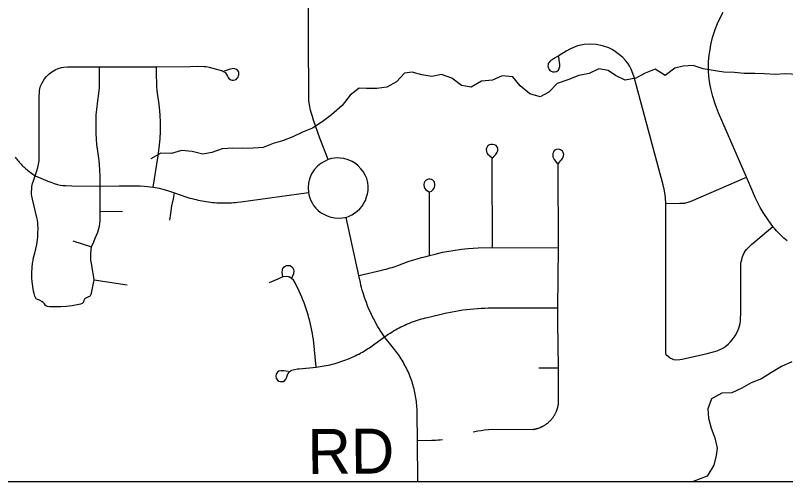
# Model space of a CAD drawing. Extents: x 0 to 34, y 0 to 22.
# Drawn here: x 4.7803 to 5.2675, y 14.1 to 14.3947 of the extents above; entities that cross this region are included whole.
import ezdxf

# ---------------------------------------------------------------- set-up
doc = ezdxf.new("R2010")
doc.units = 0
for name, color, linetype in [('GM_X_Minor_River', 7, 'Continuous'), ('GM_X_Rail_Line_Text', 7, 'Continuous'), ('GM_X_Township_Road', 7, 'Continuous'), ('GM_X_Township_Road_Text', 7, 'Continuous'), ('SH_Cut_Line', 7, 'Continuous'), ('SH_Data', 7, 'Continuous')]:
    doc.layers.add(name, color=color, linetype=linetype)

msp = doc.modelspace()

# ---------------------------------------------------------------- linework, layer by layer
at = {"layer": 'GM_X_Minor_River'}
for points in [[(5.27933, 14.3571), (5.26727, 14.35766), (5.26102, 14.35743), (5.25419, 14.35777), (5.24812, 14.35791), (5.24129, 14.35806), (5.23522, 14.35859), (5.22839, 14.35873), (5.22174, 14.35982), (5.21529, 14.36092), (5.20902, 14.36296), (5.20276, 14.36254), (5.19746, 14.36137), (5.19123, 14.35677), (5.18495, 14.36071), (5.17871, 14.35821), (5.17266, 14.35494), (5.16603, 14.35376), (5.15994, 14.35675), (5.15518, 14.35994), (5.1493, 14.36085), (5.14324, 14.35797), (5.13662, 14.35678), (5.12981, 14.35389), (5.123, 14.35157), (5.11772, 14.34622), (5.11224, 14.34315), (5.10578, 14.34519), (5.09968, 14.35009), (5.0949, 14.35594), (5.08826, 14.35646), (5.08202, 14.35376), (5.0752, 14.35315), (5.06858, 14.34931), (5.06251, 14.35041), (5.05641, 14.35492), (5.04976, 14.35734), (5.0437, 14.35616), (5.03743, 14.35707), (5.03135, 14.35892), (5.02643, 14.35813), (5.02134, 14.35278), (5.0153, 14.34933), (5.00885, 14.34853), (5.00241, 14.34848), (4.99766, 14.34864), (4.992, 14.34424), (4.98693, 14.33775), (4.98033, 14.33183), (4.97429, 14.32742), (4.96825, 14.3234), (4.96201, 14.32089), (4.95577, 14.318), (4.94934, 14.31549), (4.94328, 14.31375), (4.93704, 14.31124), (4.93078, 14.31081), (4.92415, 14.31058), (4.91789, 14.31073), (4.91107, 14.3103), (4.90463, 14.30798), (4.89876, 14.307), (4.89211, 14.30866), (4.88547, 14.30937), (4.87904, 14.30743), (4.87221, 14.30758), (4.86597, 14.30412)], [(5.27133, 14.17574), (5.2649, 14.17266), (5.25867, 14.16902), (5.25224, 14.16499), (5.24581, 14.16248), (5.23977, 14.15902), (5.23353, 14.15613), (5.22708, 14.1559), (5.22066, 14.15225), (5.21824, 14.14598), (5.21866, 14.1401), (5.2204, 14.13385), (5.22272, 14.1276), (5.22428, 14.12116), (5.22355, 14.11641), (5.22208, 14.11033), (5.21795, 14.10348), (5.20896, 14.1)]]:
    msp.add_lwpolyline(points, dxfattribs=at)
at = {"layer": 'GM_X_Rail_Line_Text'}
msp.add_lwpolyline([(6.04095, 15.63985), (5.15815, 15.63216), (4.9916, 15.62952), (4.91092, 15.62892), (4.86706, 15.62859), (4.81644, 15.62822), (4.76351, 15.62783), (4.71135, 15.62744), (4.67425, 15.62717), (4.62172, 15.62678), (4.57028, 15.6264), (4.49413, 15.62523), (4.43207, 15.62366), (4.42437, 15.62356), (4.29897, 15.62253), (4.30139, 15.38981), (4.3001, 14.71018), (4.30008, 14.70375), (4.29942, 14.35536), (4.29894, 14.1), (6.7466, 14.1)], dxfattribs=at)
at = {"layer": 'GM_X_Township_Road'}
for p, q in [((4.83385, 14.27067), (4.84795, 14.27087)), ((4.81662, 14.25217), (4.82845, 14.24832)), ((4.83018, 14.22756), (4.85103, 14.22431)), ((5.11143, 14.1719), (5.12377, 14.17192))]:
    msp.add_line(p, q, dxfattribs=at)
for points in [[(4.97807, 14.30357), (4.97292, 14.3171), (4.96892, 14.32839), (4.96815, 14.33077), (4.96738, 14.33329), (4.96701, 14.33478), (4.96626, 14.33813), (4.96591, 14.34093), (4.96584, 14.34296), (4.96577, 14.38025), (4.96577, 14.40337)], [(5.26844, 14.25217), (5.26743, 14.25303), (5.26644, 14.25391), (5.26547, 14.25481), (5.26451, 14.25572), (5.26357, 14.25665), (5.26264, 14.25759), (5.26173, 14.25855), (5.26084, 14.25953), (5.26072, 14.25966), (5.26066, 14.25974), (5.26059, 14.25981), (5.26052, 14.25989), (5.26045, 14.25997), (5.26039, 14.26004), (5.26032, 14.26012), (5.26025, 14.2602), (5.26018, 14.26027), (5.26012, 14.26035), (5.26005, 14.26043), (5.25998, 14.2605), (5.25992, 14.26058), (5.25985, 14.26066), (5.25938, 14.2612), (5.25696, 14.26476), (5.25326, 14.27018), (5.25148, 14.2732), (5.25016, 14.27575), (5.24831, 14.27962), (5.24676, 14.28326), (5.24281, 14.29239), (5.22494, 14.33317), (5.22308, 14.3382), (5.22145, 14.34339), (5.22022, 14.34842), (5.2196, 14.35159), (5.21921, 14.35445), (5.21882, 14.3591), (5.21875, 14.36204), (5.21882, 14.3656), (5.21921, 14.36947), (5.21967, 14.37287), (5.22029, 14.37612), (5.2213, 14.38076), (5.22293, 14.38587), (5.2244, 14.38951), (5.22587, 14.39268), (5.22795, 14.39681)], [(5.19455, 14.17812), (5.19313, 14.17897), (5.19235, 14.17961), (5.19185, 14.1804), (5.19163, 14.18111), (5.19163, 14.27573), (5.19153, 14.27928), (5.19135, 14.28135), (5.19071, 14.28478), (5.19006, 14.28755), (5.18757, 14.29696), (5.17325, 14.35025), (5.17161, 14.3556), (5.17081, 14.35799), (5.16983, 14.36065), (5.16872, 14.36275), (5.1677, 14.3645), (5.16621, 14.36622), (5.16449, 14.36799), (5.16239, 14.3698), (5.15993, 14.3717), (5.15786, 14.37305), (5.15565, 14.37426), (5.15174, 14.37554), (5.1476, 14.37633), (5.1439, 14.37654), (5.14005, 14.37626), (5.13592, 14.3754), (5.13147, 14.37354), (5.12879, 14.37211), (5.12435, 14.3694), (5.12135, 14.36757), (5.11989, 14.36671), (5.11904, 14.36613), (5.11839, 14.36557), (5.11786, 14.365), (5.11739, 14.36436), (5.11725, 14.36357), (5.11718, 14.36279), (5.11732, 14.36194), (5.11754, 14.3613), (5.11796, 14.36058), (5.11846, 14.35994), (5.11925, 14.35937), (5.12032, 14.35902), (5.12131, 14.35894), (5.12266, 14.35923), (5.12331, 14.35966), (5.12381, 14.36016), (5.12431, 14.36123), (5.12465, 14.36237), (5.12465, 14.36373), (5.12432, 14.36642), (5.12403, 14.3687)], [(4.79284, 14.29328), (4.7939, 14.29648), (4.79456, 14.29858), (4.795, 14.30057), (4.79533, 14.30277), (4.79539, 14.34412), (4.79547, 14.3456), (4.79561, 14.34699), (4.79577, 14.34832), (4.79627, 14.34997), (4.79699, 14.35157), (4.79782, 14.35306), (4.79881, 14.35461), (4.79991, 14.35604), (4.80168, 14.35775), (4.80339, 14.35903), (4.80549, 14.36024), (4.80742, 14.36112), (4.80952, 14.36173), (4.81101, 14.36195), (4.81327, 14.36217), (4.83348, 14.36222), (4.86952, 14.36223), (4.89088, 14.3625), (4.89519, 14.36256), (4.89972, 14.3625), (4.90099, 14.36239), (4.90286, 14.36206), (4.90529, 14.36145), (4.91132, 14.35956), (4.91203, 14.35925), (4.91269, 14.35881), (4.91323, 14.35832), (4.91374, 14.35742), (4.9144, 14.35626), (4.91495, 14.35549), (4.91539, 14.35488), (4.91595, 14.35439), (4.91667, 14.354), (4.91749, 14.35383), (4.91832, 14.35378), (4.9192, 14.35389), (4.91992, 14.35428), (4.92064, 14.35494), (4.92119, 14.35566), (4.92152, 14.35648), (4.92163, 14.3572), (4.92158, 14.35853), (4.92136, 14.35925), (4.9208, 14.36002), (4.92009, 14.36051), (4.91915, 14.36085), (4.91821, 14.36107), (4.91733, 14.36101), (4.91609, 14.36077), (4.91424, 14.36006), (4.91242, 14.35935)], [(4.83391, 14.28675), (4.83384, 14.29257), (4.83372, 14.29728), (4.83336, 14.30289), (4.83275, 14.3073), (4.83191, 14.31309), (4.83161, 14.31641), (4.83136, 14.31997), (4.8313, 14.32329), (4.83148, 14.33174), (4.83185, 14.33512), (4.83245, 14.34073), (4.83299, 14.34528), (4.83341, 14.34888), (4.8336, 14.35184), (4.83348, 14.36222)], [(4.86744, 14.28614), (4.87065, 14.3059), (4.87133, 14.31102), (4.87187, 14.31667), (4.87208, 14.32158), (4.87201, 14.32716), (4.8718, 14.33187), (4.8714, 14.33643), (4.87099, 14.34011), (4.87043, 14.34402), (4.86996, 14.34713), (4.86976, 14.34979), (4.86969, 14.35238), (4.86958, 14.35648), (4.86952, 14.36223)], [(5.0699, 14.13139), (5.07085, 14.13161), (5.07179, 14.13181), (5.07275, 14.132), (5.07488, 14.1324), (5.07706, 14.13274), (5.07957, 14.13295), (5.08219, 14.13306), (5.10774, 14.13301), (5.10807, 14.13306), (5.10839, 14.13311), (5.10872, 14.13317), (5.10904, 14.13323), (5.10936, 14.1333), (5.10968, 14.13338), (5.11, 14.13346), (5.11032, 14.13355), (5.11064, 14.13364), (5.11095, 14.13374), (5.11127, 14.13384), (5.11158, 14.13395), (5.11189, 14.13407), (5.11219, 14.13419), (5.1125, 14.13432), (5.1128, 14.13445), (5.1131, 14.13458), (5.1134, 14.13472), (5.11369, 14.13487), (5.11399, 14.13502), (5.11428, 14.13518), (5.11456, 14.13534), (5.11485, 14.13551), (5.11513, 14.13568), (5.11541, 14.13586), (5.11568, 14.13604), (5.11595, 14.13623), (5.11622, 14.13642), (5.11649, 14.13662), (5.11675, 14.13682), (5.11701, 14.13703), (5.11726, 14.13724), (5.11751, 14.13745), (5.11776, 14.13767), (5.118, 14.1379), (5.11824, 14.13812), (5.11848, 14.13836), (5.11871, 14.13859), (5.11893, 14.13883), (5.11916, 14.13907), (5.11937, 14.13932), (5.11959, 14.13957), (5.1198, 14.13983), (5.12, 14.14009), (5.1202, 14.14035), (5.1204, 14.14062), (5.12059, 14.14089), (5.12078, 14.14116), (5.12096, 14.14144), (5.12114, 14.14172), (5.12131, 14.142), (5.12148, 14.14228), (5.12164, 14.14257), (5.1218, 14.14286), (5.12195, 14.14316), (5.12209, 14.14345), (5.12224, 14.14375), (5.12237, 14.14405), (5.1225, 14.14436), (5.12263, 14.14467), (5.12275, 14.14497), (5.12286, 14.14528), (5.12297, 14.14559), (5.12308, 14.14591), (5.12318, 14.14623), (5.12327, 14.14654), (5.12336, 14.14686), (5.12344, 14.14718), (5.12352, 14.14751), (5.12359, 14.14783), (5.12365, 14.14815), (5.12371, 14.14848), (5.12376, 14.14881), (5.12381, 14.14913), (5.12385, 14.14946), (5.12389, 14.14979), (5.12377, 14.17192), (5.12347, 14.20081), (5.12343, 14.20979), (5.12382, 14.24767), (5.12356, 14.30005), (5.12383, 14.30108), (5.12445, 14.30198), (5.12501, 14.30267), (5.12542, 14.30329), (5.12632, 14.30432), (5.12687, 14.30529), (5.12701, 14.30599), (5.12715, 14.30673), (5.12708, 14.30736), (5.12687, 14.30805), (5.12632, 14.30887), (5.12577, 14.30936), (5.12508, 14.30977), (5.12439, 14.30998), (5.12356, 14.31005), (5.12259, 14.30998), (5.12184, 14.3097), (5.12115, 14.30922), (5.12059, 14.30832), (5.12032, 14.3075), (5.12018, 14.30625), (5.12025, 14.30522), (5.12059, 14.30439), (5.12107, 14.30356), (5.12321, 14.3008)], [(5.08211, 14.24802), (5.08187, 14.30145), (5.08197, 14.30409), (5.08206, 14.30453), (5.08229, 14.30484), (5.08264, 14.30513), (5.08319, 14.30574), (5.08394, 14.3066), (5.08445, 14.30727), (5.08514, 14.30815), (5.08543, 14.30906), (5.08554, 14.30992), (5.08543, 14.31061), (5.08526, 14.3113), (5.08491, 14.31193), (5.08439, 14.31239), (5.08325, 14.31296), (5.08211, 14.31319), (5.08096, 14.31313), (5.07999, 14.3129), (5.07947, 14.3125), (5.07895, 14.31198), (5.07844, 14.31113), (5.07815, 14.3101), (5.07832, 14.30866), (5.07861, 14.30792), (5.07901, 14.30729), (5.08033, 14.30597), (5.08193, 14.30457)], [(4.78014, 14.30506), (4.78064, 14.3044), (4.78115, 14.30375), (4.78167, 14.30311), (4.7822, 14.30248), (4.78274, 14.30185), (4.7833, 14.30124), (4.78386, 14.30064), (4.78444, 14.30004), (4.78502, 14.29946), (4.78562, 14.29888), (4.78623, 14.29832), (4.78684, 14.29777), (4.78747, 14.29723), (4.7881, 14.2967), (4.79284, 14.29328), (4.79649, 14.29173), (4.80074, 14.28991), (4.80278, 14.28919), (4.80482, 14.28853), (4.80692, 14.28787), (4.80875, 14.28748), (4.81029, 14.28726), (4.81197, 14.28709), (4.81606, 14.28689), (4.83391, 14.28675), (4.84598, 14.28689), (4.85599, 14.28696), (4.85919, 14.28689), (4.86199, 14.28675), (4.86744, 14.28614), (4.87126, 14.28546), (4.87439, 14.28471), (4.8778, 14.28362), (4.881, 14.28258), (4.88821, 14.28002), (4.88946, 14.27961), (4.89073, 14.27923), (4.892, 14.27887), (4.89328, 14.27853), (4.89456, 14.27822), (4.89585, 14.27792), (4.89714, 14.27765), (4.89844, 14.2774), (4.89975, 14.27718), (4.90105, 14.27697), (4.90236, 14.27679), (4.90368, 14.27663), (4.90499, 14.27649), (4.90631, 14.27638), (4.90764, 14.27629), (4.90896, 14.27622), (4.91028, 14.27618), (4.91558, 14.27623), (4.91691, 14.2763), (4.91823, 14.27639), (4.91955, 14.2765), (4.92087, 14.27664), (4.92281, 14.27689), (4.96561, 14.28272)], [(4.98946, 14.267), (4.99143, 14.26783), (4.99319, 14.26873), (4.99483, 14.26972), (4.99652, 14.27087), (4.99816, 14.27247), (4.99968, 14.27415), (5.0007, 14.27595), (5.00167, 14.27776), (5.00248, 14.27993), (5.00301, 14.28189), (5.00336, 14.28401), (5.0034, 14.28653), (5.00317, 14.28907), (5.00255, 14.29154), (5.00165, 14.29378), (5.00019, 14.29599), (4.99883, 14.29777), (4.99722, 14.29952), (4.99542, 14.30098), (4.99327, 14.30238), (4.99075, 14.30345), (4.98796, 14.30423), (4.98577, 14.30455), (4.98389, 14.30462), (4.98209, 14.30446), (4.98028, 14.30418), (4.97807, 14.30357), (4.97358, 14.3011), (4.97132, 14.29939), (4.96923, 14.29715), (4.9676, 14.29452), (4.96637, 14.29138), (4.96578, 14.28874), (4.96554, 14.28583), (4.96561, 14.28272), (4.96611, 14.28052), (4.96647, 14.27937), (4.96698, 14.27802), (4.96793, 14.27617), (4.96895, 14.27453), (4.97031, 14.27293), (4.97166, 14.27158), (4.97334, 14.27007), (4.97503, 14.26916), (4.97745, 14.26805), (4.97979, 14.26719), (4.98229, 14.26674), (4.98578, 14.26653), (4.98876, 14.26684), (4.98946, 14.267)], [(4.82469, 14.21589), (4.82408, 14.21528), (4.82359, 14.2144), (4.82331, 14.21351), (4.82298, 14.2129), (4.82254, 14.21257), (4.82143, 14.21209), (4.81622, 14.21118), (4.81245, 14.21071), (4.80908, 14.21048), (4.80549, 14.21039), (4.80195, 14.21043), (4.80059, 14.21062), (4.79994, 14.21095), (4.79943, 14.21137), (4.79873, 14.21239), (4.79793, 14.21328), (4.7971, 14.21393), (4.79565, 14.21459), (4.79434, 14.2151), (4.7935, 14.21557), (4.79303, 14.21627), (4.79266, 14.21724), (4.7922, 14.21893), (4.79182, 14.22047), (4.79126, 14.22336), (4.79089, 14.2263), (4.7907, 14.22886), (4.79061, 14.23218), (4.79084, 14.2353), (4.79117, 14.23801), (4.79149, 14.23983), (4.79182, 14.24156), (4.79254, 14.24447), (4.79317, 14.24706), (4.79383, 14.24991), (4.79434, 14.2529), (4.79453, 14.255), (4.79458, 14.25658), (4.79467, 14.26036), (4.7946, 14.26205), (4.79444, 14.26363), (4.7942, 14.2652), (4.79392, 14.26703), (4.7928, 14.27147), (4.79189, 14.27496), (4.79103, 14.27846), (4.7907, 14.28033), (4.79056, 14.28168), (4.79065, 14.28649), (4.79103, 14.28836), (4.79168, 14.29022), (4.79284, 14.29328)], [(5.04232, 14.24291), (5.04214, 14.28071), (5.04219, 14.28259), (5.0422, 14.28291), (5.04221, 14.28306), (5.04231, 14.28315), (5.04255, 14.28324), (5.04347, 14.28368), (5.04446, 14.2846), (5.04538, 14.2859), (5.04561, 14.28697), (5.04568, 14.28811), (5.04545, 14.28911), (5.04515, 14.2898), (5.04438, 14.29048), (5.04347, 14.29094), (5.0427, 14.29109), (5.04187, 14.29109), (5.04095, 14.29094), (5.04003, 14.29048), (5.03927, 14.28972), (5.03889, 14.28895), (5.03866, 14.28811), (5.03866, 14.2875), (5.03896, 14.28621), (5.03927, 14.28537), (5.03995, 14.28437), (5.04206, 14.28311)], [(5.19163, 14.27573), (5.2006, 14.2759), (5.20353, 14.27608), (5.20589, 14.27655), (5.20771, 14.27717), (5.24281, 14.29239)], [(4.82469, 14.21589), (4.82552, 14.21644), (4.82668, 14.21693), (4.82729, 14.21721), (4.82778, 14.21765), (4.82817, 14.21848), (4.82839, 14.2192), (4.83018, 14.22756), (4.82966, 14.23054), (4.82913, 14.23389), (4.82859, 14.23675), (4.82808, 14.23999), (4.82801, 14.24222), (4.82808, 14.2444), (4.82845, 14.24832), (4.82982, 14.25162), (4.83081, 14.25386), (4.83243, 14.25772), (4.83312, 14.25996), (4.83349, 14.26139), (4.83374, 14.26325), (4.83386, 14.265), (4.83392, 14.26692), (4.83385, 14.27067), (4.83391, 14.28675)], [(4.87794, 14.26534), (4.87858, 14.26943), (4.87935, 14.27441), (4.88021, 14.27868), (4.881, 14.28258)], [(5.03488, 14.1), (5.03465, 14.12604), (5.03451, 14.14254), (5.03446, 14.14486), (5.0344, 14.14602), (5.03433, 14.14717), (5.03423, 14.14833), (5.03412, 14.14948), (5.03398, 14.15063), (5.03383, 14.15178), (5.03365, 14.15293), (5.03345, 14.15407), (5.03324, 14.15521), (5.033, 14.15634), (5.03275, 14.15747), (5.03248, 14.1586), (5.03218, 14.15972), (5.03187, 14.16084), (5.03153, 14.16195), (5.03118, 14.16305), (5.03081, 14.16415), (5.03042, 14.16524), (5.03001, 14.16632), (5.02958, 14.1674), (5.02913, 14.16847), (5.02866, 14.16953), (5.02818, 14.17058), (5.02767, 14.17162), (5.02715, 14.17266), (5.02661, 14.17368), (5.02605, 14.1747), (5.02548, 14.17571), (5.02488, 14.1767), (5.02427, 14.17769), (5.02365, 14.17866), (5.02301, 14.17963), (5.02235, 14.18058), (5.02168, 14.18152), (5.02098, 14.18245), (5.02028, 14.18336), (5.01956, 14.18427), (5.01862, 14.1854), (5.01691, 14.18748), (5.01589, 14.18878), (5.01489, 14.19009), (5.01386, 14.1915), (5.01297, 14.19277), (5.01204, 14.19414), (5.01114, 14.19552), (5.01026, 14.19692), (5.00941, 14.19833), (5.00858, 14.19976), (5.00778, 14.2012), (5.007, 14.20265), (5.00625, 14.20412), (5.00552, 14.20561), (5.00483, 14.2071), (5.00415, 14.2086), (5.00351, 14.21012), (5.00289, 14.21165), (5.00229, 14.21318), (5.00173, 14.21473), (5.00119, 14.21628), (5.00068, 14.21784), (5.0002, 14.21942), (4.99974, 14.221), (4.99931, 14.22259), (4.99891, 14.22418), (4.99854, 14.22579), (4.99754, 14.23033), (4.98946, 14.267)], [(5.19455, 14.17812), (5.19539, 14.17772), (5.19655, 14.17719), (5.19776, 14.17698), (5.20068, 14.17719), (5.20196, 14.17741), (5.21793, 14.18091), (5.22097, 14.18174), (5.2241, 14.18267), (5.2278, 14.18437), (5.22958, 14.18559), (5.2313, 14.18701), (5.23249, 14.18817), (5.23372, 14.18951), (5.2355, 14.19214), (5.23692, 14.19449), (5.23785, 14.19691), (5.23871, 14.19991), (5.23893, 14.20147), (5.23906, 14.20325), (5.23915, 14.20589), (5.23908, 14.23455), (5.23914, 14.23624), (5.23927, 14.23831), (5.2397, 14.24009), (5.24006, 14.24159), (5.24063, 14.24308), (5.24134, 14.24458), (5.24198, 14.24565), (5.24277, 14.24664), (5.24359, 14.24754), (5.2459, 14.24978), (5.25938, 14.2612)], [(4.99754, 14.23033), (5.01219, 14.2337), (5.01348, 14.234), (5.01475, 14.23433), (5.01602, 14.23467), (5.01728, 14.23504), (5.01854, 14.23544), (5.01979, 14.23585), (5.02212, 14.23669), (5.026, 14.23811), (5.02878, 14.23906), (5.03158, 14.23996), (5.03439, 14.24082), (5.03722, 14.24162), (5.04005, 14.24238), (5.04232, 14.24291), (5.04589, 14.24376), (5.05055, 14.24493), (5.05725, 14.24618), (5.0624, 14.24687), (5.06676, 14.24727), (5.07311, 14.24773), (5.08211, 14.24802), (5.12382, 14.24767)], [(4.94937, 14.22945), (4.94912, 14.23231), (4.94921, 14.2337), (4.94953, 14.23464), (4.95006, 14.23546), (4.95088, 14.23619), (4.95183, 14.23656), (4.95293, 14.23666), (4.95403, 14.23653), (4.95526, 14.23584), (4.95586, 14.23508), (4.95623, 14.23411), (4.95636, 14.23313), (4.95617, 14.23143), (4.95542, 14.22948), (4.95501, 14.22842)], [(4.97057, 14.17241), (4.96883, 14.18973), (4.96852, 14.1917), (4.96817, 14.19366), (4.96779, 14.19561), (4.96738, 14.19756), (4.96694, 14.19953), (4.96648, 14.2015), (4.96597, 14.20345), (4.96542, 14.20536), (4.96482, 14.20727), (4.9642, 14.20918), (4.96356, 14.21107), (4.96289, 14.21294), (4.96218, 14.21481), (4.96145, 14.21667), (4.96069, 14.21851), (4.95989, 14.22034), (4.95724, 14.2257), (4.9562, 14.22724), (4.95501, 14.22842), (4.95425, 14.22888), (4.95321, 14.22938), (4.95192, 14.22963), (4.94937, 14.22945), (4.94795, 14.22888), (4.94628, 14.22803), (4.94386, 14.22683), (4.9408, 14.22554)], [(4.95283, 14.16953), (4.95, 14.16999), (4.94848, 14.17007), (4.94703, 14.16984), (4.94603, 14.16923), (4.94535, 14.168), (4.94512, 14.16671), (4.94535, 14.16533), (4.94603, 14.16411), (4.94688, 14.16342), (4.94793, 14.16321), (4.9497, 14.16327), (4.95069, 14.16381), (4.95138, 14.16472), (4.95184, 14.16556), (4.95245, 14.1674), (4.95283, 14.16839), (4.95344, 14.1693), (4.9543, 14.16998), (4.95522, 14.17033), (4.95679, 14.17082), (4.95872, 14.17121), (4.9597, 14.17133), (4.97057, 14.17241), (4.97438, 14.1729), (4.97564, 14.17311), (4.9769, 14.17334), (4.97816, 14.17359), (4.97941, 14.17386), (4.98066, 14.17416), (4.98191, 14.17448), (4.98315, 14.17483), (4.98438, 14.1752), (4.98561, 14.1756), (4.98684, 14.17603), (4.98805, 14.17647), (4.98926, 14.17693), (4.99047, 14.17741), (4.99166, 14.1779), (4.99284, 14.17841), (4.99402, 14.17894), (4.99519, 14.17949), (4.99635, 14.18006), (4.9975, 14.18064), (4.99864, 14.18125), (4.99882, 14.18134), (4.99979, 14.18188), (5.00091, 14.18254), (5.00202, 14.18321), (5.00311, 14.1839), (5.00419, 14.18461), (5.00774, 14.1871), (5.01386, 14.1915), (5.0151, 14.19237), (5.01619, 14.19311), (5.0173, 14.19383), (5.01842, 14.19453), (5.01955, 14.19521), (5.02069, 14.19588), (5.02184, 14.19652), (5.023, 14.19714), (5.02418, 14.19774), (5.02536, 14.19832), (5.02655, 14.19888), (5.02775, 14.19942), (5.02965, 14.20022), (5.03087, 14.2007), (5.03209, 14.20116), (5.03333, 14.2016), (5.03458, 14.20202), (5.03584, 14.20242), (5.0371, 14.20279), (5.03837, 14.20315), (5.03965, 14.20347), (5.04094, 14.20378), (5.05214, 14.20637), (5.05662, 14.20734), (5.05888, 14.20777), (5.06115, 14.20815), (5.06343, 14.2085), (5.06571, 14.2088), (5.06799, 14.20907), (5.07028, 14.20929), (5.07257, 14.20947), (5.07486, 14.20962), (5.07716, 14.20972), (5.07945, 14.20978), (5.12343, 14.20979)], [(5.03465, 14.12604), (5.04369, 14.1261), (5.04501, 14.12615), (5.04634, 14.12624), (5.04765, 14.12634), (5.04897, 14.12647), (5.05042, 14.12664)]]:
    msp.add_lwpolyline(points, dxfattribs=at)
at = {"layer": 'SH_Cut_Line'}
msp.add_lwpolyline([(2.1, 20.39416), (2.1, 14.1), (8.9, 14.1)], dxfattribs=at)
at = {"layer": 'SH_Data'}
msp.add_line((2.1, 14.1), (8.9, 14.1), dxfattribs=at)

# ---------------------------------------------------------------- texts
at = {"layer": 'GM_X_Township_Road_Text'}
msp.add_text('RD', height=0.028409, rotation=0.4937, dxfattribs=at).set_placement((4.96519, 14.10472))

doc.saveas('drawing.dxf')
